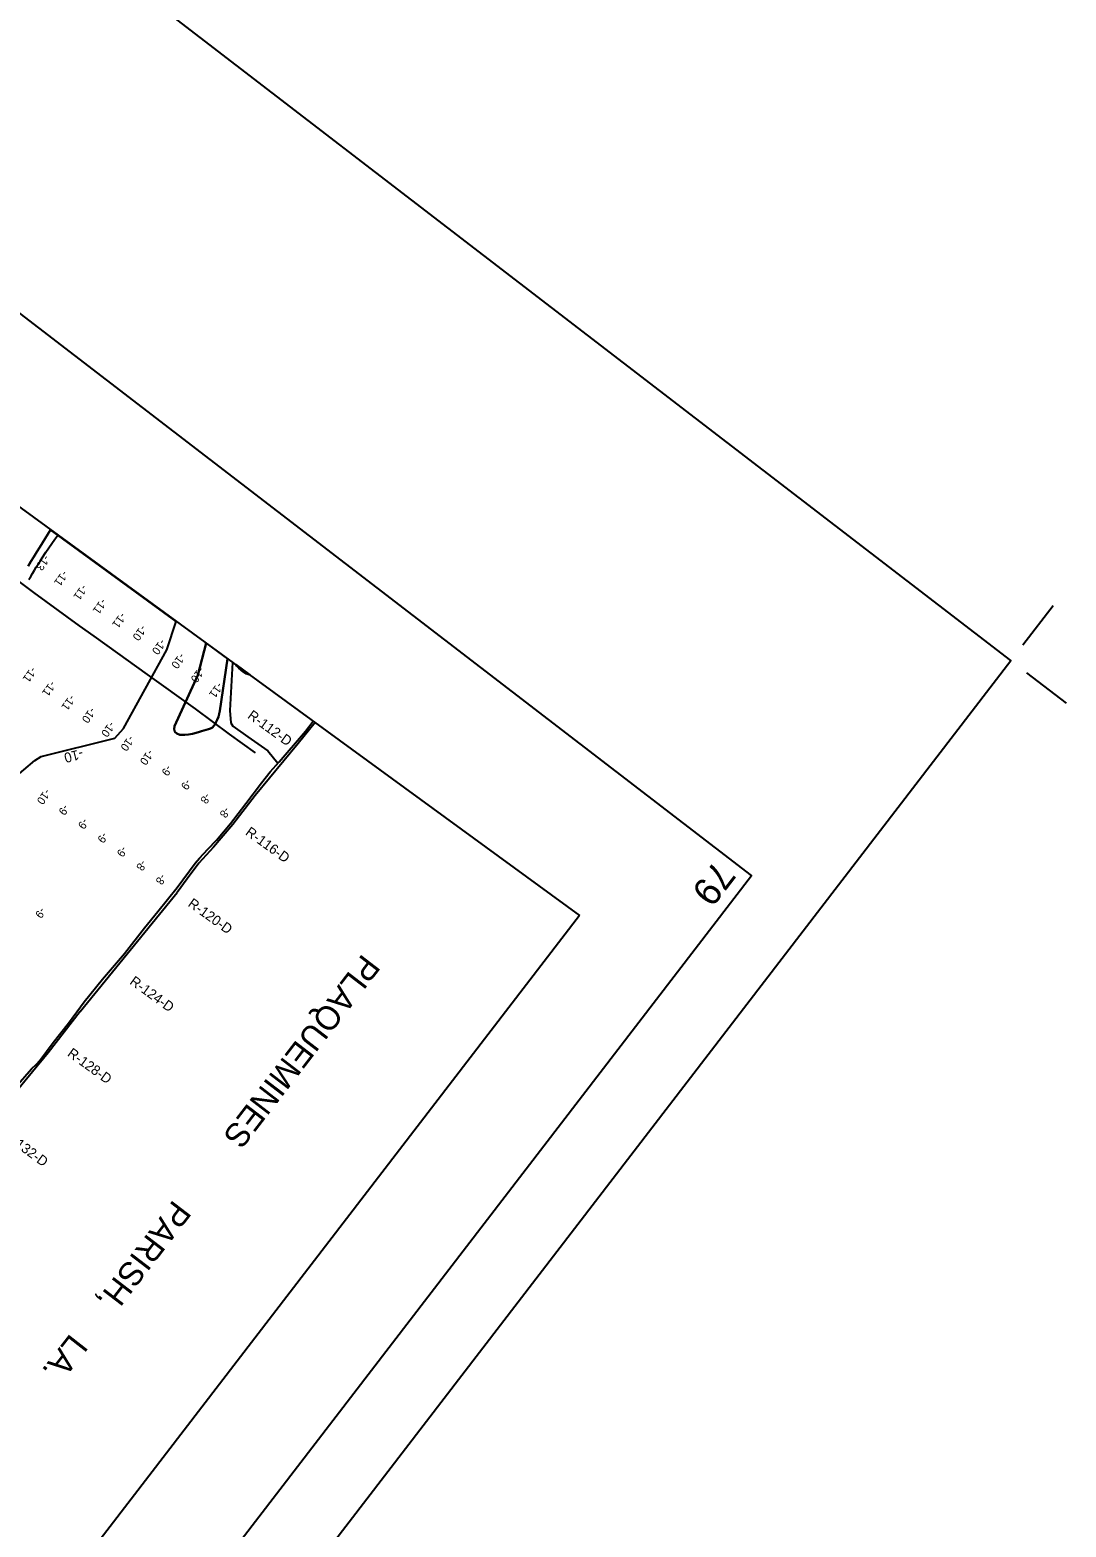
# Model space of a CAD drawing. Extents: x 3879599 to 3900814, y 146526 to 168888.
# Drawn here: x 3896475 to 3900814, y 157667 to 163934 of the extents above; entities that cross this region are included whole.
import ezdxf

# ---------------------------------------------------------------- set-up
doc = ezdxf.new("R2010")
doc.units = 0
for name, color, linetype in [('G-ANNO-NPLT', 7, 'Continuous'), ('V-ANNO-DIMS', 7, 'Continuous'), ('V-ANNO-SYMB', 7, 'Continuous'), ('V-ANNO-TEXT', 7, 'Continuous'), ('V-GRID-FRAM', 7, 'Continuous'), ('V-LEVE-TOET', 7, 'Continuous'), ('V-RIVR-EDGE', 7, 'Continuous'), ('V-RIVR-JETY', 7, 'Continuous'), ('V-RIVR-RANG', 7, 'Continuous'), ('V-RIVR-RANG-IDEN', 7, 'Continuous'), ('V-TOPO-DPTH', 7, 'Continuous'), ('V-TOPO-GNAM-IDEN', 7, 'Continuous'), ('V-TOPO-MINR', 7, 'Continuous'), ('V-TOPO-MINR-IDEN', 7, 'Continuous'), ('V-WETL-SWMP', 7, 'Continuous')]:
    doc.layers.add(name, color=color, linetype=linetype)

msp = doc.modelspace()

# ---------------------------------------------------------------- linework, layer by layer
at = {"layer": 'G-ANNO-NPLT'}
msp.add_lwpolyline([(3891001.3, 168656.7), (3879830.2, 154120), (3889411.2, 146757.2), (3900582.4, 161294)], close=True, dxfattribs=at)
at = {"layer": 'V-ANNO-DIMS'}
for p, q in [((3900633.1, 161360.1), (3900760.1, 161525.2)), ((3900648.4, 161243.2), (3900813.6, 161116.3))]:
    msp.add_line(p, q, dxfattribs=at)
at = {"layer": 'V-ANNO-SYMB'}
msp.add_lwpolyline([(3890411.2, 167376), (3880331.9, 154259.9), (3889417.3, 147278), (3899496.7, 160394.1), (3890411.2, 167376)], dxfattribs=at)
at = {"layer": 'V-GRID-FRAM'}
msp.add_lwpolyline([(3898776.6, 160226.4), (3889730.7, 148455.2), (3882888.9, 153284.4), (3891901.5, 165241.3), (3898776.6, 160226.4)], dxfattribs=at)
at = {"layer": 'V-LEVE-TOET'}
msp.add_lwpolyline([(3897419.3, 160907.4), (3897311, 160985.3), (3897169.2, 161092), (3896967.9, 161235.4), (3896798.9, 161357), (3896744.2, 161395.8), (3896682.3, 161439.8), (3896491.3, 161579.2), (3896414.2, 161636.9)], dxfattribs=at)
at = {"layer": 'V-RIVR-EDGE'}
msp.add_lwpolyline([(3897323.4, 161286.5), (3897313.1, 161084.8), (3897316.2, 161033.2), (3897325.6, 161019.1), (3897388.1, 160975.4), (3897470.9, 160916), (3897513.8, 160863.9)], dxfattribs=at)
at = {"layer": 'V-RIVR-JETY'}
msp.add_line((3896685.1, 159825), (3897092.5, 160323.4), dxfattribs=at)
for points in [[(3896416.9, 159509.8), (3896482.2, 159584.8), (3896502.8, 159603.9), (3896516.5, 159619.9), (3896572.6, 159694.9), (3896637.6, 159776.8), (3896702.1, 159865), (3896778.8, 159960.4), (3896871.5, 160068.1), (3896954.7, 160175), (3897010.7, 160244.1), (3897092.2, 160344.6), (3897167.3, 160445.2), (3897185.9, 160466.8), (3897220.1, 160504.3), (3897256, 160542.2), (3897314.5, 160612), (3897379.4, 160696.2), (3897445.6, 160782), (3897481.9, 160827.9), (3897518.6, 160869.4), (3897628.7, 160999.1), (3897661.8, 161041)], [(3897669.6, 161035.3), (3897598, 160946.3), (3897418.9, 160729.6), (3897325.3, 160608.3), (3897243.4, 160512.2), (3897182.9, 160445.2), (3897134.1, 160380.9), (3897092.5, 160323.4)], [(3896685.1, 159825), (3896552.3, 159652.6), (3896486.6, 159572), (3896396.2, 159463), (3896299, 159332.1), (3896188.8, 159199.2), (3896085.2, 159073.9), (3895927.5, 158886.4), (3895842.3, 158773.4), (3895735.8, 158643.4), (3895597.5, 158475.4), (3895483.7, 158330.1), (3895356.2, 158170.5), (3895213, 157988.1), (3895118.6, 157873.6), (3895027.3, 157764.3)]]:
    msp.add_lwpolyline(points, dxfattribs=at)
at = {"layer": 'V-TOPO-DPTH'}
for p, q in [((3897087.9, 161458.2), (3896561.9, 161841.9)), ((3897214, 161366.2), (3897302.8, 161301.4))]:
    msp.add_line(p, q, dxfattribs=at)
for points in [[(3896561.9, 161841.9), (3896516.7, 161769), (3896504.3, 161749), (3896492, 161728.9), (3896479.8, 161708.8), (3896467.6, 161688.7)], [(3896561.9, 161841.9), (3896516.7, 161769), (3896504.3, 161749), (3896492, 161728.9), (3896479.8, 161708.8), (3896467.6, 161688.7)], [(3896403.4, 160798.1), (3896495.6, 160875.2), (3896521.9, 160892.8), (3896830.3, 160969.6), (3896867.3, 161010), (3897048.8, 161339.6), (3897087.9, 161458.2)], [(3897082.4, 160995.4), (3897079.8, 161006.2), (3897081, 161019.3), (3897178.8, 161233.3), (3897214, 161366.2)], [(3897302.8, 161301.4), (3897270.5, 161083.1), (3897267.9, 161070.4), (3897264.5, 161057.9), (3897259.8, 161045.9), (3897254.2, 161034.2), (3897251.1, 161028.4), (3897245.7, 161020.8), (3897239.3, 161014.5), (3897231.4, 161010), (3897222.7, 161006.7), (3897213.1, 161004.3), (3897203.6, 161001.8), (3897194.2, 160999), (3897184.9, 160996), (3897172, 160991.7), (3897156.1, 160987.3), (3897140, 160984.2), (3897123.7, 160982.9), (3897107.2, 160982.9), (3897102.9, 160983.1), (3897090.8, 160988.1), (3897082.4, 160995.4)]]:
    msp.add_lwpolyline(points, dxfattribs=at)
at = {"layer": 'V-TOPO-MINR'}
for points in [[(3896467.6, 161688.7), (3896479.8, 161708.8), (3896492, 161728.9), (3896504.3, 161749), (3896516.7, 161769), (3896561.9, 161841.9)], [(3896471.4, 161633.4), (3896479, 161646.3), (3896486.7, 161659.1), (3896494.4, 161672), (3896502.1, 161684.8), (3896509.5, 161697.2), (3896513.6, 161703.9), (3896517.6, 161710.4), (3896521.8, 161716.9), (3896526, 161723.4), (3896542, 161747.8), (3896554.5, 161766.3), (3896567.1, 161784.7), (3896580.2, 161802.8), (3896592.5, 161819.6)], [(3896403.4, 160798.1), (3896495.6, 160875.2), (3896521.9, 160892.8), (3896830.3, 160969.6), (3896867.3, 161010), (3897048.8, 161339.6), (3897087.9, 161458.2)], [(3897214, 161366.2), (3897178.8, 161233.3), (3897081, 161019.3), (3897079.8, 161006.2), (3897082.4, 160995.4)], [(3897082.4, 160995.4), (3897090.8, 160988.1), (3897102.9, 160983.1), (3897107.2, 160982.9), (3897123.7, 160982.9), (3897140, 160984.2), (3897156.1, 160987.3), (3897172, 160991.7), (3897184.9, 160996), (3897194.2, 160999), (3897203.6, 161001.8), (3897213.1, 161004.3), (3897222.7, 161006.7), (3897231.4, 161010), (3897239.3, 161014.5), (3897245.7, 161020.8), (3897251.1, 161028.4), (3897254.2, 161034.2), (3897259.8, 161045.9), (3897264.5, 161057.9), (3897267.9, 161070.4), (3897270.5, 161083.1), (3897302.8, 161301.4)]]:
    msp.add_lwpolyline(points, dxfattribs=at)
at = {"layer": 'V-WETL-SWMP'}
for p, q in [((3897337.2, 161277.8), (3897396.8, 161234.3)), ((3897342.2, 161270.9), (3897337.2, 161277.8)), ((3897349.8, 161262.8), (3897342.2, 161270.9)), ((3897368.4, 161246.5), (3897349.8, 161262.8)), ((3897380.5, 161238.7), (3897368.4, 161246.5)), ((3897393.8, 161234.6), (3897380.5, 161238.7)), ((3897394.2, 161236.2), (3897393.1, 161234.8)), ((3897396.8, 161234.3), (3897393.8, 161234.6))]:
    msp.add_line(p, q, dxfattribs=at)

# ---------------------------------------------------------------- texts
at = {"layer": 'V-ANNO-TEXT'}
msp.add_text('79', height=115, rotation=232.45871, dxfattribs=at).set_placement((3899345.4, 160462.6))
at = {"layer": 'V-RIVR-RANG'}
for s, rotation, p in [('-13', 234.03833, (3896536.4, 161738.7)), ('-11', 234.03833, (3896612.5, 161673.3)), ('-11', 234.03833, (3896693.5, 161614.7)), ('-11', 234.03833, (3896774.6, 161556.2)), ('-11', 234.03833, (3896855.7, 161497.7)), ('-10', 234.03833, (3896941.1, 161445.2)), ('-10', 234.03833, (3897022.2, 161386.6)), ('-10', 234.03833, (3897103.3, 161328.1)), ('-11', 233.94833, (3896481.3, 161270.3)), ('-10', 234.03833, (3897184.4, 161269.6)), ('-11', 233.94833, (3896562.3, 161211.7)), ('-11', 234.03833, (3897261.2, 161205.1)), ('-11', 233.94833, (3896643.3, 161153)), ('-10', 233.94833, (3896728.7, 161100.4)), ('-10', 233.94833, (3896809.7, 161041.7)), ('-10', 233.94833, (3896890.6, 160983)), ('-10', 233.94833, (3896971.6, 160924.4)), ('-9', 233.94833, (3897047.8, 160859.1)), ('-9', 233.94833, (3897128.8, 160800.5)), ('-10', 234.20833, (3896540, 160759.6)), ('-8', 233.94833, (3897210, 160742.2)), ('-9', 234.20833, (3896616.4, 160694.6)), ('-9', 234.20833, (3896697.7, 160636.4)), ('-8', 233.94833, (3897291, 160683.5)), ('-9', 234.20833, (3896779, 160578.1)), ('-9', 234.20833, (3896860.2, 160519.8)), ('-8', 234.20833, (3896941.7, 160461.8)), ('-8', 234.20833, (3897023, 160403.5)), ('-9', 233.97833, (3896518.7, 160263.3))]:
    msp.add_text(s, height=33.5, rotation=rotation, dxfattribs=at).set_placement(p)
at = {"layer": 'V-RIVR-RANG-IDEN'}
for s, rotation, p in [('R-112-D', 324.17901, (3897383.5, 161056.2)), ('R-116-D', 324.09225, (3897374.3, 160567.8)), ('R-120-D', 324.35065, (3897133.7, 160268.6)), ('R-124-D', 324.12097, (3896889.9, 159942.9)), ('R-128-D', 324.2005, (3896629, 159641.8)), ('R-132-D', 323.82559, (3896362.8, 159296.5))]:
    msp.add_text(s, height=41.5, rotation=rotation, dxfattribs=at).set_placement(p)
at = {"layer": 'V-TOPO-GNAM-IDEN'}
for s, rotation, p in [('PLAQUEMINES', 232.47061, (3897868.5, 160070.4)), ('PARISH,', 232.57061, (3897076.8, 159040.7)), ('LA.', 231.97061, (3896645.1, 158480.5))]:
    msp.add_text(s, height=100, rotation=rotation, dxfattribs=at).set_placement(p)
at = {"layer": 'V-TOPO-MINR-IDEN'}
msp.add_text('-10', height=41.5, rotation=193.99468, dxfattribs=at).set_placement((3896692.9, 160924.7))

doc.saveas('drawing.dxf')
